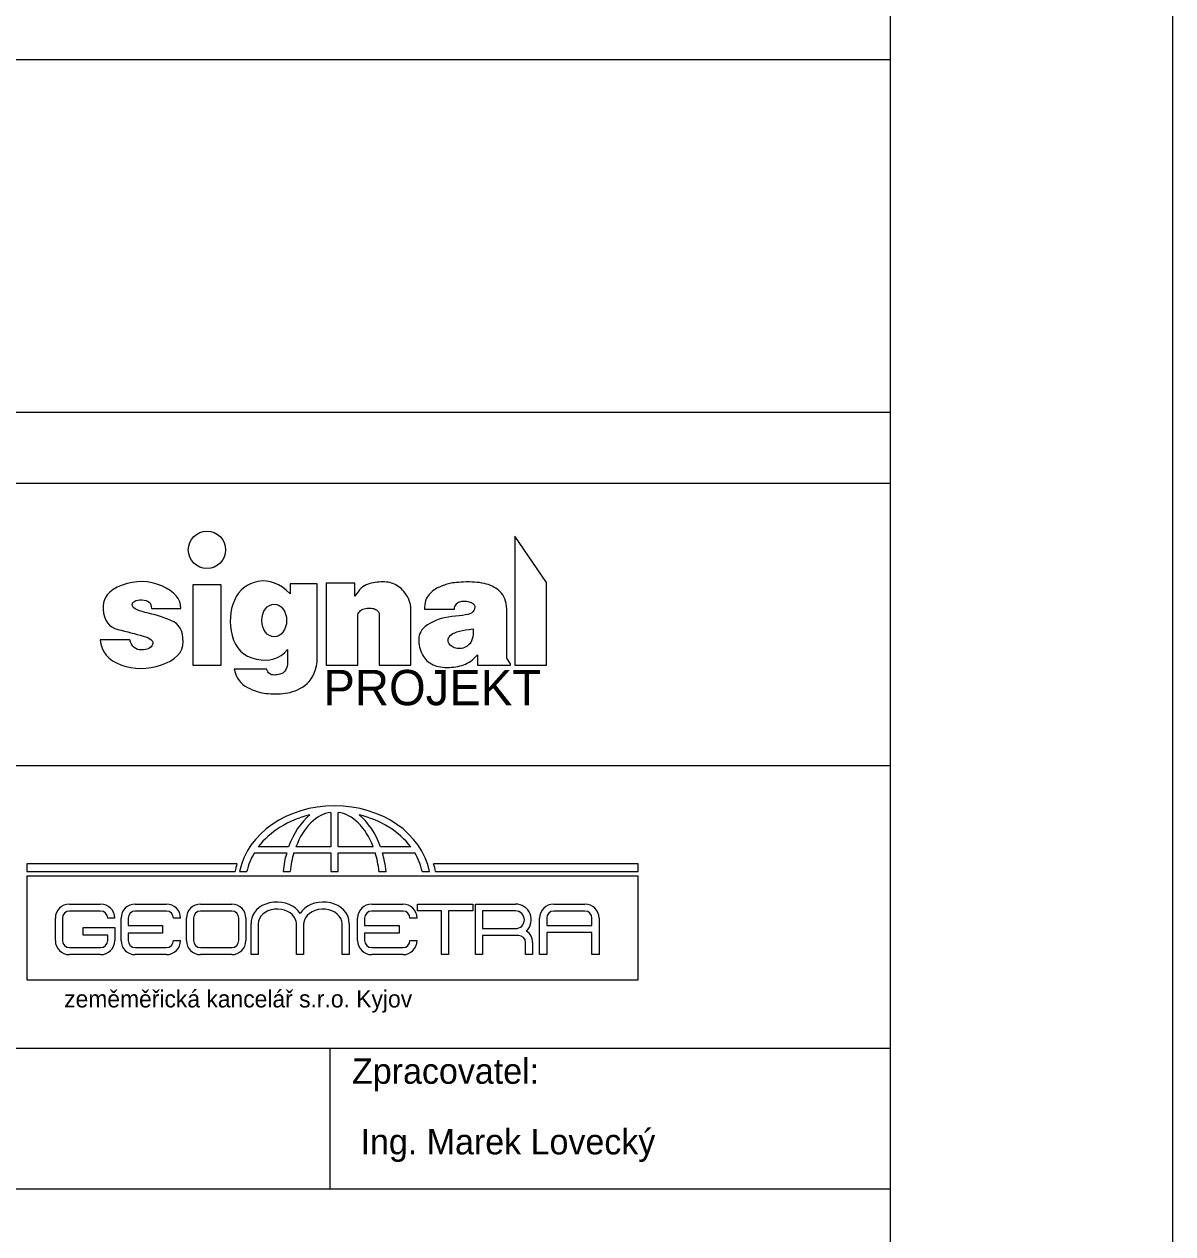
# Model space of a CAD drawing. Extents: x 1391 to 5528, y -6194 to 565.
# Drawn here: x 4054.2 to 4135.6, y -4584.2 to -4498.5 of the extents above; entities that cross this region are included whole.
import ezdxf

# ---------------------------------------------------------------- set-up
doc = ezdxf.new("R2010")
doc.units = 0
for name, color, linetype in [('Default', 7, 'Continuous'), ('Vrstva 1', 7, 'Continuous'), ('Vrstva 11', 7, 'Continuous'), ('Vrstva 17', 7, 'Continuous'), ('Vrstva 5', 7, 'Continuous'), ('Vrstva 6', 7, 'Continuous')]:
    doc.layers.add(name, color=color, linetype=linetype)

msp = doc.modelspace()

# ---------------------------------------------------------------- linework, layer by layer
at = {"layer": 'Default'}
msp.add_lwpolyline([(3925.563, -4683.032), (4135.563, -4683.032), (4135.563, -4386.032), (3925.563, -4386.032)], close=True, dxfattribs=at)
at = {"layer": 'Vrstva 1'}
msp.add_lwpolyline([(3945.563, -4406.032), (4115.563, -4406.032), (4115.563, -4666.032), (3945.563, -4666.032)], close=True, dxfattribs=at)
at = {"layer": 'Vrstva 11'}
for points in [[(4091.228, -4543.911), (4091.228, -4538.071), (4088.988, -4534.791), (4088.988, -4543.911), (4091.228, -4543.911)], [(4062.499, -4544.146), (4062.861, -4544.13), (4063.228, -4544.082), (4063.599, -4544.003), (4063.975, -4543.893), (4064.329, -4543.757), (4064.637, -4543.6), (4064.898, -4543.424), (4065.112, -4543.228), (4065.28, -4543.013), (4065.4, -4542.777), (4065.474, -4542.521), (4065.5, -4542.245), (4065.49, -4541.971), (4065.451, -4541.722), (4065.385, -4541.498), (4065.291, -4541.299), (4065.17, -4541.124), (4065.021, -4540.974), (4064.844, -4540.849), (4064.639, -4540.748), (4064.42, -4540.662), (4064.198, -4540.58), (4063.973, -4540.503), (4063.747, -4540.43), (4063.518, -4540.361), (4063.287, -4540.297), (4063.054, -4540.237), (4062.818, -4540.182), (4062.596, -4540.127), (4062.405, -4540.068), (4062.244, -4540.005), (4062.114, -4539.938), (4062.014, -4539.867), (4061.945, -4539.792), (4061.906, -4539.712), (4061.897, -4539.629), (4061.914, -4539.55), (4061.95, -4539.481), (4062.006, -4539.423), (4062.082, -4539.376), (4062.178, -4539.339), (4062.294, -4539.314), (4062.429, -4539.299), (4062.585, -4539.296), (4062.74, -4539.306), (4062.875, -4539.336), (4062.99, -4539.383), (4063.085, -4539.449), (4063.16, -4539.532), (4063.214, -4539.635), (4063.249, -4539.755), (4063.263, -4539.894), (4065.342, -4539.894), (4065.323, -4539.652), (4065.261, -4539.422), (4065.156, -4539.205), (4065.008, -4539.001), (4064.817, -4538.809), (4064.583, -4538.631), (4064.307, -4538.465), (4063.987, -4538.311), (4063.645, -4538.182), (4063.3, -4538.087), (4062.952, -4538.027), (4062.602, -4538.002), (4062.249, -4538.012), (4061.894, -4538.057), (4061.535, -4538.137), (4061.174, -4538.252), (4060.836, -4538.394), (4060.547, -4538.557), (4060.306, -4538.74), (4060.114, -4538.944), (4059.971, -4539.168), (4059.876, -4539.413), (4059.83, -4539.679), (4059.832, -4539.965), (4059.872, -4540.246), (4059.938, -4540.498), (4060.03, -4540.72), (4060.148, -4540.913), (4060.293, -4541.076), (4060.464, -4541.21), (4060.661, -4541.315), (4060.885, -4541.389), (4061.12, -4541.449), (4061.351, -4541.509), (4061.578, -4541.568), (4061.802, -4541.627), (4062.023, -4541.686), (4062.239, -4541.744), (4062.452, -4541.802), (4062.662, -4541.86), (4062.854, -4541.92), (4063.016, -4541.984), (4063.146, -4542.053), (4063.246, -4542.126), (4063.314, -4542.204), (4063.352, -4542.287), (4063.359, -4542.374), (4063.335, -4542.465), (4063.289, -4542.553), (4063.228, -4542.629), (4063.152, -4542.694), (4063.062, -4542.747), (4062.958, -4542.789), (4062.84, -4542.819), (4062.707, -4542.837), (4062.559, -4542.844), (4062.411, -4542.833), (4062.275, -4542.8), (4062.152, -4542.744), (4062.04, -4542.666), (4061.942, -4542.565), (4061.855, -4542.441), (4061.781, -4542.294), (4061.72, -4542.126), (4059.639, -4542.126), (4059.683, -4542.433), (4059.767, -4542.715), (4059.89, -4542.973), (4060.052, -4543.206), (4060.254, -4543.416), (4060.496, -4543.601), (4060.778, -4543.762), (4061.099, -4543.899), (4061.442, -4544.008), (4061.79, -4544.085), (4062.142, -4544.131), (4062.499, -4544.146)], [(4068.188, -4543.911), (4068.188, -4538.231), (4066.188, -4538.231), (4066.188, -4543.911), (4068.188, -4543.911)], [(4072.047, -4545.954), (4072.216, -4545.95), (4072.386, -4545.941), (4072.558, -4545.928), (4072.731, -4545.91), (4072.905, -4545.883), (4073.079, -4545.844), (4073.253, -4545.793), (4073.426, -4545.729), (4073.6, -4545.654), (4073.772, -4545.566), (4073.945, -4545.466), (4074.117, -4545.354), (4074.282, -4545.225), (4074.43, -4545.072), (4074.563, -4544.896), (4074.679, -4544.698), (4074.78, -4544.476), (4074.865, -4544.231), (4074.934, -4543.963), (4074.988, -4543.671), (4074.988, -4538.151), (4073.068, -4538.151), (4073.068, -4538.871), (4072.802, -4538.617), (4072.531, -4538.404), (4072.257, -4538.232), (4071.978, -4538.101), (4071.695, -4538.011), (4071.407, -4537.962), (4071.116, -4537.954), (4070.82, -4537.988), (4070.533, -4538.056), (4070.267, -4538.153), (4070.024, -4538.278), (4069.802, -4538.432), (4069.602, -4538.614), (4069.423, -4538.825), (4069.267, -4539.065), (4069.132, -4539.333), (4069.022, -4539.619), (4068.937, -4539.912), (4068.878, -4540.212), (4068.845, -4540.519), (4068.838, -4540.834), (4068.857, -4541.155), (4068.901, -4541.484), (4068.972, -4541.82), (4069.072, -4542.144), (4069.205, -4542.434), (4069.37, -4542.692), (4069.568, -4542.918), (4069.799, -4543.11), (4070.062, -4543.271), (4070.358, -4543.398), (4070.687, -4543.493), (4071.023, -4543.551), (4071.342, -4543.568), (4071.643, -4543.545), (4071.926, -4543.481), (4072.191, -4543.376), (4072.438, -4543.23), (4072.668, -4543.044), (4072.88, -4542.817), (4072.88, -4543.894), (4072.861, -4543.982), (4072.838, -4544.063), (4072.81, -4544.139), (4072.778, -4544.209), (4072.742, -4544.274), (4072.701, -4544.333), (4072.655, -4544.386), (4072.605, -4544.433), (4072.55, -4544.475), (4072.487, -4544.511), (4072.417, -4544.542), (4072.34, -4544.567), (4072.256, -4544.588), (4072.165, -4544.602), (4072.067, -4544.612), (4071.962, -4544.616), (4071.858, -4544.61), (4071.765, -4544.592), (4071.682, -4544.56), (4071.609, -4544.515), (4071.546, -4544.456), (4071.493, -4544.385), (4071.451, -4544.3), (4071.418, -4544.202), (4069.111, -4544.202), (4069.18, -4544.429), (4069.264, -4544.638), (4069.361, -4544.828), (4069.472, -4545), (4069.596, -4545.152), (4069.735, -4545.286), (4069.887, -4545.402), (4070.053, -4545.498), (4070.225, -4545.581), (4070.396, -4545.655), (4070.565, -4545.721), (4070.733, -4545.778), (4070.899, -4545.826), (4071.064, -4545.866), (4071.227, -4545.897), (4071.389, -4545.92), (4071.551, -4545.935), (4071.715, -4545.946), (4071.88, -4545.952), (4072.047, -4545.954)], [(4081.628, -4543.911), (4081.628, -4540.111), (4081.624, -4539.942), (4081.61, -4539.778), (4081.586, -4539.622), (4081.55, -4539.472), (4081.504, -4539.328), (4081.447, -4539.191), (4081.379, -4539.061), (4081.301, -4538.937), (4081.216, -4538.821), (4081.129, -4538.713), (4081.04, -4538.613), (4080.949, -4538.521), (4080.856, -4538.438), (4080.761, -4538.363), (4080.664, -4538.296), (4080.565, -4538.237), (4080.462, -4538.186), (4080.356, -4538.141), (4080.245, -4538.104), (4080.13, -4538.073), (4080.011, -4538.05), (4079.887, -4538.033), (4079.759, -4538.024), (4079.627, -4538.021), (4079.493, -4538.024), (4079.361, -4538.032), (4079.229, -4538.045), (4079.099, -4538.063), (4078.97, -4538.086), (4078.842, -4538.114), (4078.716, -4538.147), (4078.59, -4538.184), (4078.467, -4538.233), (4078.345, -4538.297), (4078.226, -4538.379), (4078.11, -4538.476), (4077.996, -4538.59), (4077.884, -4538.721), (4077.775, -4538.868), (4077.668, -4539.031), (4077.668, -4538.111), (4075.628, -4538.111), (4075.628, -4543.911), (4077.868, -4543.911), (4077.868, -4540.351), (4077.902, -4540.26), (4077.946, -4540.18), (4078.001, -4540.109), (4078.065, -4540.048), (4078.139, -4539.996), (4078.223, -4539.955), (4078.317, -4539.924), (4078.421, -4539.903), (4078.527, -4539.89), (4078.628, -4539.884), (4078.723, -4539.883), (4078.814, -4539.888), (4078.899, -4539.9), (4078.978, -4539.917), (4079.053, -4539.941), (4079.122, -4539.971), (4079.184, -4540.005), (4079.238, -4540.044), (4079.284, -4540.086), (4079.321, -4540.131), (4079.35, -4540.181), (4079.371, -4540.234), (4079.383, -4540.291), (4079.388, -4540.351), (4079.388, -4543.911), (4081.628, -4543.911)], [(4084.19, -4544.076), (4084.352, -4544.073), (4084.51, -4544.064), (4084.663, -4544.05), (4084.812, -4544.03), (4084.956, -4544.004), (4085.097, -4543.972), (4085.233, -4543.935), (4085.364, -4543.892), (4085.493, -4543.841), (4085.62, -4543.779), (4085.746, -4543.707), (4085.869, -4543.625), (4085.991, -4543.532), (4086.112, -4543.429), (4086.23, -4543.315), (4086.348, -4543.191), (4086.348, -4543.911), (4088.668, -4543.911), (4088.668, -4543.831), (4088.428, -4543.431), (4088.428, -4539.951), (4088.401, -4539.747), (4088.365, -4539.557), (4088.32, -4539.381), (4088.265, -4539.22), (4088.201, -4539.073), (4088.127, -4538.941), (4088.043, -4538.823), (4087.95, -4538.72), (4087.849, -4538.627), (4087.742, -4538.541), (4087.628, -4538.462), (4087.508, -4538.39), (4087.382, -4538.325), (4087.25, -4538.267), (4087.111, -4538.216), (4086.966, -4538.172), (4086.814, -4538.134), (4086.655, -4538.102), (4086.489, -4538.075), (4086.315, -4538.055), (4086.135, -4538.04), (4085.947, -4538.03), (4085.751, -4538.027), (4085.549, -4538.029), (4085.35, -4538.035), (4085.166, -4538.043), (4084.997, -4538.054), (4084.843, -4538.066), (4084.703, -4538.081), (4084.578, -4538.099), (4084.467, -4538.118), (4084.372, -4538.14), (4084.283, -4538.163), (4084.194, -4538.189), (4084.104, -4538.217), (4084.013, -4538.246), (4083.921, -4538.278), (4083.829, -4538.311), (4083.737, -4538.347), (4083.643, -4538.384), (4083.55, -4538.426), (4083.458, -4538.474), (4083.366, -4538.529), (4083.276, -4538.592), (4083.187, -4538.661), (4083.099, -4538.736), (4083.012, -4538.819), (4082.926, -4538.909), (4082.845, -4539.006), (4082.776, -4539.113), (4082.718, -4539.229), (4082.67, -4539.355), (4082.633, -4539.49), (4082.607, -4539.635), (4082.592, -4539.788), (4082.588, -4539.951), (4084.708, -4539.951), (4084.723, -4539.855), (4084.747, -4539.768), (4084.78, -4539.69), (4084.821, -4539.621), (4084.872, -4539.561), (4084.93, -4539.511), (4084.998, -4539.469), (4085.073, -4539.437), (4085.154, -4539.413), (4085.235, -4539.395), (4085.317, -4539.384), (4085.399, -4539.379), (4085.481, -4539.381), (4085.565, -4539.389), (4085.648, -4539.404), (4085.732, -4539.425), (4085.813, -4539.451), (4085.884, -4539.478), (4085.947, -4539.508), (4086, -4539.54), (4086.045, -4539.574), (4086.082, -4539.611), (4086.109, -4539.649), (4086.128, -4539.69), (4086.14, -4539.733), (4086.145, -4539.778), (4086.144, -4539.827), (4086.136, -4539.878), (4086.122, -4539.933), (4086.103, -4539.99), (4086.076, -4540.049), (4086.044, -4540.112), (4085.993, -4540.173), (4085.912, -4540.229), (4085.801, -4540.28), (4085.659, -4540.325), (4085.487, -4540.365), (4085.285, -4540.4), (4085.052, -4540.429), (4084.789, -4540.453), (4084.517, -4540.48), (4084.258, -4540.518), (4084.01, -4540.565), (4083.775, -4540.624), (4083.553, -4540.693), (4083.342, -4540.772), (4083.144, -4540.862), (4082.958, -4540.963), (4082.789, -4541.071), (4082.641, -4541.184), (4082.513, -4541.301), (4082.407, -4541.423), (4082.321, -4541.549), (4082.256, -4541.68), (4082.212, -4541.815), (4082.189, -4541.955), (4082.181, -4542.096), (4082.182, -4542.236), (4082.192, -4542.375), (4082.211, -4542.513), (4082.239, -4542.65), (4082.276, -4542.785), (4082.322, -4542.92), (4082.377, -4543.053), (4082.44, -4543.181), (4082.51, -4543.3), (4082.587, -4543.41), (4082.671, -4543.512), (4082.761, -4543.605), (4082.859, -4543.688), (4082.964, -4543.763), (4083.075, -4543.829), (4083.193, -4543.887), (4083.317, -4543.937), (4083.447, -4543.979), (4083.584, -4544.014), (4083.726, -4544.041), (4083.875, -4544.06), (4084.03, -4544.072), (4084.19, -4544.076)], [(4084.906, -4542.731), (4084.803, -4542.711), (4084.708, -4542.682), (4084.622, -4542.646), (4084.543, -4542.603), (4084.472, -4542.551), (4084.409, -4542.492), (4084.354, -4542.426), (4084.307, -4542.351), (4084.273, -4542.273), (4084.255, -4542.196), (4084.254, -4542.12), (4084.27, -4542.045), (4084.302, -4541.971), (4084.351, -4541.898), (4084.417, -4541.826), (4084.5, -4541.754), (4084.603, -4541.686), (4084.732, -4541.623), (4084.886, -4541.565), (4085.065, -4541.513), (4085.269, -4541.466), (4085.498, -4541.424), (4085.753, -4541.387), (4086.032, -4541.356), (4086.037, -4541.554), (4086.028, -4541.736), (4086.006, -4541.902), (4085.972, -4542.052), (4085.924, -4542.186), (4085.864, -4542.303), (4085.79, -4542.404), (4085.704, -4542.49), (4085.611, -4542.561), (4085.515, -4542.62), (4085.418, -4542.668), (4085.319, -4542.704), (4085.219, -4542.728), (4085.116, -4542.741), (4085.012, -4542.742), (4084.906, -4542.731)]]:
    msp.add_lwpolyline(points, dxfattribs=at)
msp.add_circle((4067.188, -4535.751), 1.32, dxfattribs=at)
msp.add_ellipse((4071.948, -4540.751), major_axis=(0, 1.16), ratio=0.758621, dxfattribs=at)
at = {"layer": 'Vrstva 17'}
for p, q in [((4075.958, -4554.345), (4075.958, -4556.791)), ((4076.465, -4556.791), (4076.465, -4554.343)), ((4070.545, -4557.202), (4072.832, -4557.202)), ((4072.965, -4556.791), (4070.82, -4556.791)), ((4073.342, -4557.202), (4075.958, -4557.202)), ((4075.958, -4556.791), (4073.482, -4556.791)), ((4075.958, -4557.202), (4075.958, -4558.523)), ((4078.96, -4556.791), (4076.465, -4556.791)), ((4076.465, -4558.523), (4076.465, -4557.202)), ((4076.465, -4557.202), (4079.099, -4557.202)), ((4081.622, -4556.791), (4079.477, -4556.791)), ((4079.609, -4557.202), (4081.897, -4557.202)), ((4069.314, -4557.991), (4054.433, -4557.991)), ((4054.433, -4557.991), (4054.433, -4558.523)), ((4097.712, -4557.991), (4083.233, -4557.991)), ((4097.712, -4558.523), (4097.712, -4557.991)), ((4097.71, -4558.867), (4054.427, -4558.867)), ((4054.427, -4558.867), (4054.427, -4566.205)), ((4054.433, -4558.523), (4069.176, -4558.523)), ((4069.502, -4558.523), (4070.019, -4558.523)), ((4072.575, -4558.523), (4073.075, -4558.523)), ((4075.958, -4558.523), (4076.465, -4558.523)), ((4079.366, -4558.523), (4079.866, -4558.523)), ((4082.423, -4558.523), (4082.94, -4558.523)), ((4083.371, -4558.523), (4097.712, -4558.523)), ((4097.71, -4566.205), (4097.71, -4558.867)), ((4057.452, -4560.833), (4059.663, -4560.833)), ((4062.108, -4560.833), (4064.319, -4560.833)), ((4066.732, -4560.833), (4068.943, -4560.833)), ((4078.851, -4560.833), (4081.061, -4560.833)), ((4086.188, -4560.833), (4089.032, -4560.833)), ((4091.736, -4560.833), (4093.947, -4560.833)), ((4059.663, -4561.332), (4057.452, -4561.332)), ((4064.319, -4561.332), (4062.108, -4561.332)), ((4068.943, -4561.332), (4066.732, -4561.332)), ((4081.061, -4561.332), (4078.851, -4561.332)), ((4083.794, -4564.415), (4083.794, -4561.32)), ((4084.297, -4561.32), (4084.297, -4564.415)), ((4089.032, -4561.322), (4086.692, -4561.322)), ((4086.692, -4561.322), (4086.692, -4562.572)), ((4093.947, -4561.332), (4091.736, -4561.332)), ((4056.454, -4563.417), (4056.454, -4561.831)), ((4056.953, -4561.831), (4056.953, -4563.417)), ((4058.427, -4563.039), (4058.427, -4562.494)), ((4058.427, -4562.494), (4060.66, -4562.494)), ((4060.66, -4561.831), (4060.162, -4561.831)), ((4060.66, -4562.494), (4060.66, -4563.417)), ((4061.11, -4563.417), (4061.11, -4561.831)), ((4061.609, -4561.831), (4061.609, -4562.342)), ((4061.609, -4562.342), (4064.052, -4562.342)), ((4064.052, -4562.342), (4064.052, -4562.886)), ((4065.317, -4561.831), (4064.818, -4561.831)), ((4065.734, -4563.417), (4065.734, -4561.831)), ((4066.233, -4561.831), (4066.233, -4563.417)), ((4069.442, -4563.417), (4069.442, -4561.831)), ((4069.941, -4561.831), (4069.941, -4563.417)), ((4070.313, -4564.415), (4070.313, -4562.23)), ((4070.814, -4562.23), (4070.814, -4564.415)), ((4073.533, -4564.415), (4073.533, -4562.23)), ((4074.033, -4562.23), (4074.033, -4564.415)), ((4076.752, -4564.415), (4076.752, -4562.23)), ((4077.253, -4562.23), (4077.253, -4564.415)), ((4077.853, -4563.417), (4077.853, -4561.831)), ((4078.352, -4561.831), (4078.352, -4562.342)), ((4078.352, -4562.342), (4080.795, -4562.342)), ((4080.795, -4562.342), (4080.795, -4562.886)), ((4082.059, -4561.831), (4081.56, -4561.831)), ((4086.692, -4562.572), (4089.032, -4562.572)), ((4090.738, -4564.415), (4090.738, -4561.831)), ((4091.237, -4561.831), (4091.237, -4562.34)), ((4091.237, -4562.34), (4094.446, -4562.34)), ((4094.446, -4562.34), (4094.446, -4561.831)), ((4094.945, -4561.831), (4094.945, -4564.415)), ((4060.162, -4563.039), (4058.427, -4563.039)), ((4060.162, -4563.417), (4060.162, -4563.039)), ((4064.052, -4562.886), (4061.609, -4562.886)), ((4061.609, -4562.886), (4061.609, -4563.417)), ((4064.818, -4563.417), (4065.317, -4563.417)), ((4080.795, -4562.886), (4078.352, -4562.886)), ((4078.352, -4562.886), (4078.352, -4563.417)), ((4081.56, -4563.417), (4082.059, -4563.417)), ((4089.032, -4563.061), (4086.692, -4563.061)), ((4089.247, -4563.064), (4089.032, -4563.061)), ((4094.446, -4562.843), (4091.237, -4562.843)), ((4091.237, -4562.843), (4091.237, -4564.415)), ((4094.446, -4564.415), (4094.446, -4562.843)), ((4057.452, -4563.916), (4059.663, -4563.916)), ((4062.108, -4563.916), (4064.319, -4563.916)), ((4066.732, -4563.916), (4068.943, -4563.916)), ((4078.851, -4563.916), (4081.061, -4563.916)), ((4089.746, -4564.415), (4089.746, -4563.564)), ((4090.244, -4563.564), (4090.244, -4564.415)), ((4059.663, -4564.415), (4057.452, -4564.415)), ((4064.319, -4564.415), (4062.108, -4564.415)), ((4068.943, -4564.415), (4066.732, -4564.415)), ((4070.814, -4564.415), (4070.313, -4564.415)), ((4074.033, -4564.415), (4073.533, -4564.415)), ((4077.253, -4564.415), (4076.752, -4564.415)), ((4081.061, -4564.415), (4078.851, -4564.415)), ((4084.297, -4564.415), (4083.794, -4564.415)), ((4090.244, -4564.415), (4089.746, -4564.415)), ((4091.237, -4564.415), (4090.738, -4564.415)), ((4094.945, -4564.415), (4094.446, -4564.415)), ((4054.427, -4566.205), (4097.71, -4566.205))]:
    msp.add_line(p, q, dxfattribs=at)
for points in [[(4083.794, -4561.32), (4082.096, -4561.32), (4082.096, -4560.833), (4086.009, -4560.833)], [(4086.009, -4560.833), (4086.009, -4561.32), (4084.297, -4561.32)], [(4086.692, -4563.061), (4086.692, -4564.415), (4086.188, -4564.415), (4086.188, -4560.833)]]:
    msp.add_lwpolyline(points, dxfattribs=at)
for centre, radius, start, end in [((4057.452, -4561.831), 0.998, 90, 180), ((4059.663, -4561.831), 0.998, 360, 90), ((4062.108, -4561.831), 0.998, 90, 180), ((4064.319, -4561.831), 0.998, 360, 90), ((4066.732, -4561.831), 0.998, 90, 180), ((4068.943, -4561.831), 0.998, 360, 90), ((4078.851, -4561.831), 0.998, 90, 180), ((4081.061, -4561.831), 0.998, 360, 90), ((4089.032, -4561.947), 1.114, 314.45734, 90), ((4091.736, -4561.831), 0.998, 90, 180), ((4093.947, -4561.831), 0.998, 360, 90), ((4057.452, -4561.831), 0.499, 90, 180), ((4059.663, -4561.831), 0.499, 0, 90), ((4062.108, -4561.831), 0.499, 90, 180), ((4064.319, -4561.831), 0.499, 0, 90), ((4066.732, -4561.831), 0.499, 90, 180), ((4068.943, -4561.831), 0.499, 0, 90), ((4078.851, -4561.831), 0.499, 90, 180), ((4081.061, -4561.831), 0.499, 0, 90), ((4089.032, -4561.947), 0.625, 270, 90), ((4091.736, -4561.831), 0.499, 90, 180), ((4093.947, -4561.831), 0.499, 0, 90), ((4072.25, -4562.28), 1.938, 166.96576, 178.52091), ((4072.579, -4562.294), 0.957, 3.86486, 22.41569), ((4075.266, -4562.352), 1.238, 162.61388, 174.3506), ((4075.315, -4562.28), 1.938, 1.47909, 13.03424), ((4057.452, -4563.417), 0.998, 180, 270), ((4057.452, -4563.417), 0.499, 180, 270), ((4059.663, -4563.417), 0.998, 270, 0), ((4059.663, -4563.417), 0.499, 270, 0), ((4062.108, -4563.417), 0.998, 180, 270), ((4062.108, -4563.417), 0.499, 180, 270), ((4064.319, -4563.417), 0.998, 270, 0), ((4064.319, -4563.417), 0.499, 270, 0), ((4066.732, -4563.417), 0.998, 180, 270), ((4066.732, -4563.417), 0.499, 180, 270), ((4068.943, -4563.417), 0.998, 270, 0), ((4068.943, -4563.417), 0.499, 270, 0), ((4078.851, -4563.417), 0.998, 180, 270), ((4078.851, -4563.417), 0.499, 180, 270), ((4081.061, -4563.417), 0.998, 270, 0), ((4081.061, -4563.417), 0.499, 270, 0), ((4089.247, -4563.564), 0.499, 0, 90), ((4089.247, -4563.564), 0.998, 360, 55.44734)]:
    msp.add_arc(centre, radius, start, end, dxfattribs=at)
for centre, major_axis, ratio, start_param, end_param in [((4076.221, -4559.395), (-6.804, 0), 0.811768, 3.300239, 6.124539), ((4076.221, -4559.395), (-6.296, 0), 0.804826, 4.992897, 5.743383), ((4076.221, -4559.395), (0, 5.524), 0.668443, 0.491666, 1.079789), ((4076.221, -4559.395), (0, 5.067), 0.630136, 0.08224, 1.030995), ((4076.221, -4559.395), (0, 5.067), 0.630136, 5.252191, 6.206521), ((4076.221, -4559.395), (0, 5.524), 0.668443, 5.203397, 5.79152), ((4076.221, -4559.395), (-6.296, 0), 0.804826, 3.681394, 4.431881), ((4076.221, -4559.395), (-6.296, 0), 0.804826, 5.835664, 6.110118), ((4076.221, -4559.395), (0, 5.524), 0.668443, 1.16256, 1.41215), ((4076.221, -4559.395), (0, 5.067), 0.630136, 1.123275, 1.397729), ((4076.221, -4559.395), (0, 5.067), 0.630136, 4.885456, 5.159911), ((4076.221, -4559.395), (0, 5.524), 0.668443, 4.871035, 5.120625), ((4076.221, -4559.395), (-6.296, 0), 0.804826, 3.31466, 3.589114), ((4075.895, -4559.395), (-6.804, 0), 0.811768, 6.026233, 6.124539), ((4076.653, -4559.395), (-6.804, 0), 0.811768, 3.300239, 3.398545), ((4072.142, -4562.074), (1.805, 0), 0.766187, 0.429647, 2.97338), ((4075.424, -4562.074), (-1.805, 0), 0.766187, 3.309805, 5.853538), ((4072.167, -4562.23), (1.354, 0), 0.766187, 0.29376, 3.141593), ((4075.398, -4562.23), (-1.354, 0), 0.766187, 3.141593, 6.041607)]:
    msp.add_ellipse(centre, major_axis=major_axis, ratio=ratio, start_param=start_param, end_param=end_param, dxfattribs=at)
at = {"layer": 'Vrstva 5'}
msp.add_lwpolyline([(3945.563, -4501.032), (4115.563, -4501.032), (4115.563, -4526.032), (3945.563, -4526.032)], close=True, dxfattribs=at)
at = {"layer": 'Vrstva 6'}
for p, q in [((3945.563, -4551.032), (4115.563, -4551.032)), ((3945.563, -4571.032), (4115.563, -4571.032)), ((4075.913, -4581.032), (4075.913, -4571.032))]:
    msp.add_line(p, q, dxfattribs=at)
msp.add_lwpolyline([(3945.563, -4531.032), (4115.563, -4531.032), (4115.563, -4581.032), (3945.563, -4581.032)], close=True, dxfattribs=at)

# ---------------------------------------------------------------- texts
at = {"layer": 'Vrstva 11'}
msp.add_text('PROJEKT', height=2.5, dxfattribs=at).set_placement((4075.428, -4546.755))
at = {"layer": 'Vrstva 17'}
msp.add_text('zeměměřická kancelář s.r.o. Kyjov', height=1.20984, dxfattribs=at).set_placement((4057.079, -4568.154))
at = {"layer": 'Vrstva 6'}
for s, p in [('Zpracovatel:', (4077.459, -4573.559)), ('Ing. Marek Lovecký', (4078.06, -4578.559))]:
    msp.add_text(s, height=1.8, dxfattribs=at).set_placement(p)

doc.saveas('drawing.dxf')
